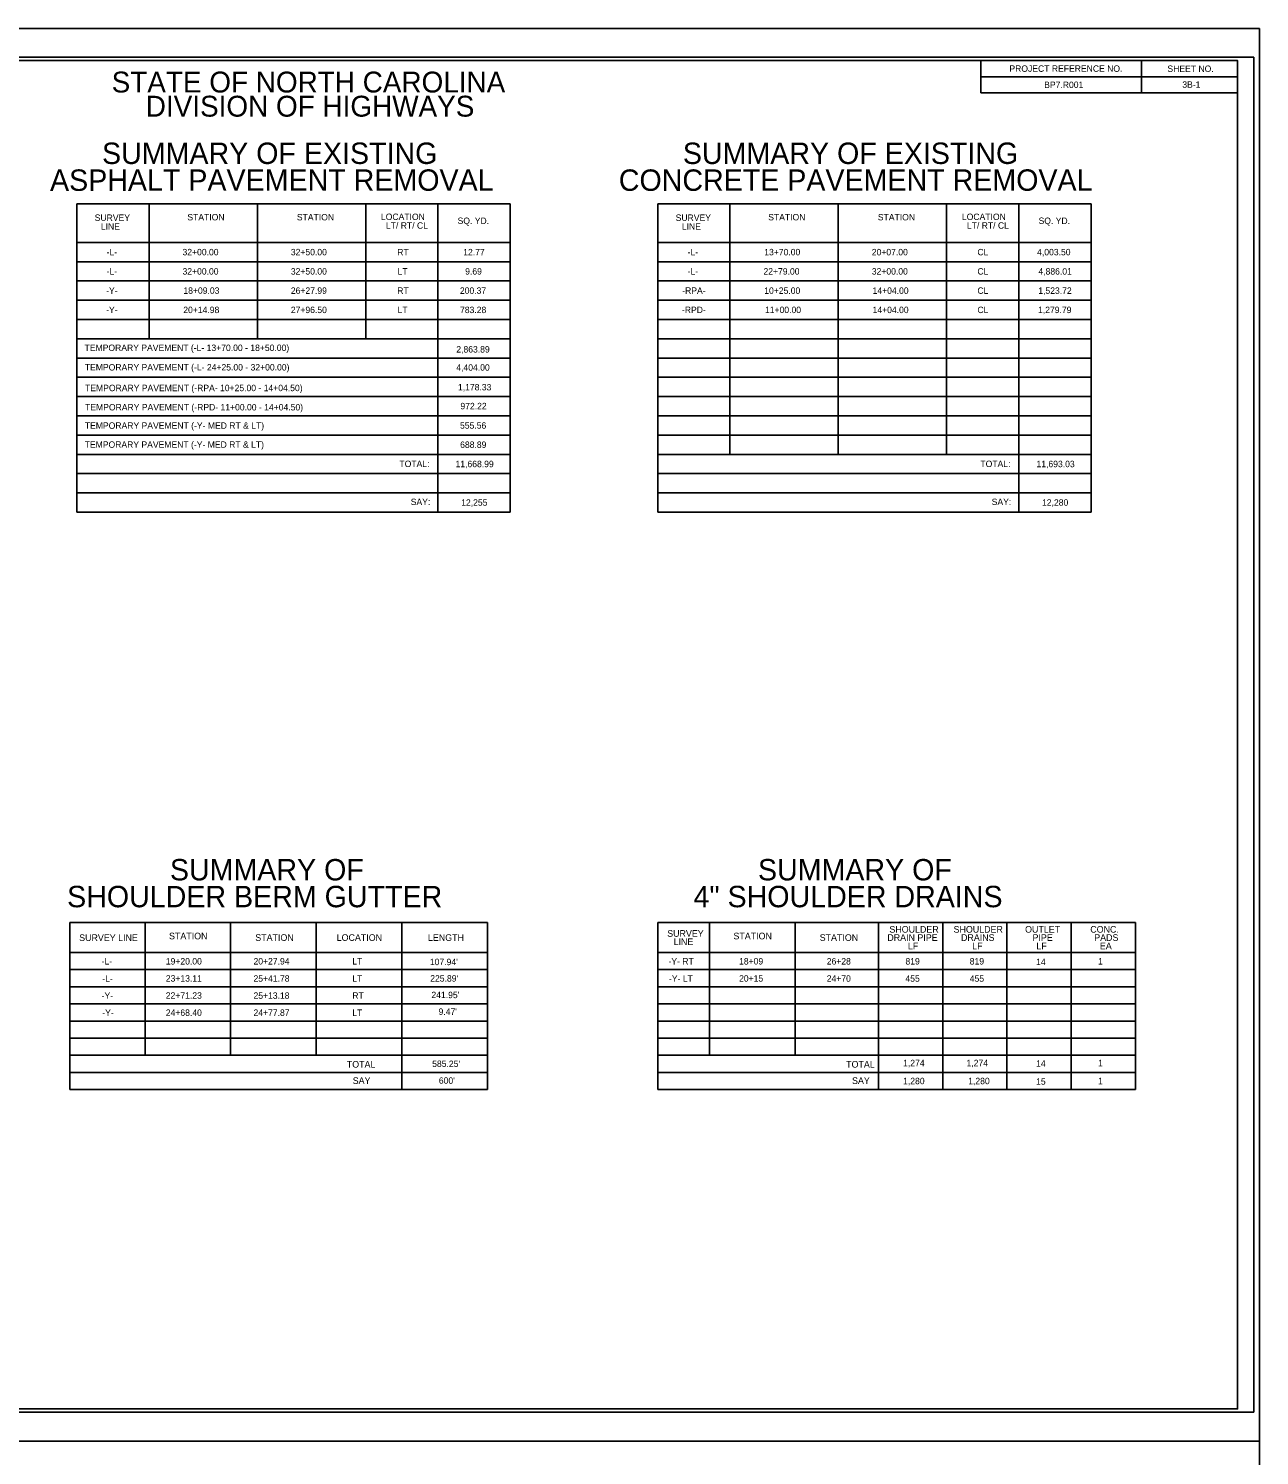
# Model space of a CAD drawing. Extents: x 1730642 to 1732326, y 538795 to 540995.
# Drawn here: x 1731367 to 1732326, y 539884 to 540995 of the extents above; entities that cross this region are included whole.
import ezdxf

# ---------------------------------------------------------------- set-up
doc = ezdxf.new("R2010")
doc.units = 0
for name, color, linetype in [('Default', 7, 'Continuous'), ('Old_Level_40', 7, 'Continuous'), ('Old_Level_44', 7, 'Continuous'), ('Sheet Cutting Line CELL', 7, 'Continuous'), ('Sheet Data Field CELL', 7, 'Continuous'), ('Sheet Pipe Summary CELL', 7, 'Continuous'), ('Sheet Pipe Summary Grid CELL', 7, 'Continuous'), ('Sheet Summary Combination CELL', 7, 'Continuous'), ('Sheet Summary Earthwork CELL', 7, 'Continuous'), ('Sheet Summary Guardrail CELL', 7, 'Continuous')]:
    doc.layers.add(name, color=color, linetype=linetype)

msp = doc.modelspace()

# ---------------------------------------------------------------- linework, layer by layer
at = {"layer": 'Old_Level_40'}
for p, q in [((1732233.5, 540970.4), (1732233.5, 540945.4)), ((1732108.5, 540957.9), (1732308.5, 540957.9)), ((1732108.5, 540945.4), (1732308.5, 540945.4)), ((1731573.6, 540858.8), (1731573.6, 540858.8)), ((1731581.1, 540858.6), (1731581.1, 540858.6)), ((1731592, 540858.9), (1731592, 540858.9)), ((1731598.7, 540858.8), (1731598.7, 540858.8)), ((1732026.2, 540858.8), (1732026.2, 540858.8)), ((1732033.7, 540858.6), (1732033.7, 540858.6)), ((1732044.6, 540858.9), (1732044.6, 540858.9)), ((1732051.3, 540858.8), (1732051.3, 540858.8))]:
    msp.add_line(p, q, dxfattribs=at)
for points in [[(1732308.5, 540970.4), (1730808.5, 540970.4), (1730808.5, 539920.4), (1732308.5, 539920.4)], [(1732108.5, 540970.4), (1732308.5, 540970.4), (1732308.5, 540945.4), (1732108.5, 540945.4)]]:
    msp.add_lwpolyline(points, close=True, dxfattribs=at)
at = {"layer": 'Old_Level_44'}
for p, q in [((1731404.1, 540858.8), (1731741.7, 540858.8)), ((1731404.1, 540858.8), (1731404.1, 540618.8)), ((1731460.4, 540858.8), (1731460.4, 540753.8)), ((1731544.8, 540858.8), (1731544.8, 540753.8)), ((1731629.2, 540858.8), (1731629.2, 540753.8)), ((1731685.5, 540858.8), (1731685.5, 540618.8)), ((1731741.7, 540858.8), (1731741.7, 540618.8)), ((1731856.7, 540858.8), (1732194.3, 540858.8)), ((1731856.7, 540858.8), (1731856.7, 540618.8)), ((1731913, 540858.8), (1731913, 540663.8)), ((1731997.4, 540858.8), (1731997.4, 540663.8)), ((1732081.8, 540858.8), (1732081.8, 540663.8)), ((1732138, 540858.8), (1732138, 540618.8)), ((1732194.3, 540858.8), (1732194.3, 540618.8)), ((1731404.1, 540828.8), (1731741.7, 540828.8)), ((1731856.7, 540828.8), (1732194.3, 540828.8)), ((1731404.1, 540813.8), (1731741.7, 540813.8)), ((1731856.7, 540813.8), (1732194.3, 540813.8)), ((1731404.1, 540798.8), (1731741.7, 540798.8)), ((1731856.7, 540798.8), (1732194.3, 540798.8)), ((1731404.1, 540783.8), (1731741.7, 540783.8)), ((1731856.7, 540783.8), (1732194.3, 540783.8)), ((1731404.1, 540768.8), (1731741.7, 540768.8)), ((1731856.7, 540768.8), (1732194.3, 540768.8)), ((1731404.1, 540753.8), (1731741.7, 540753.8)), ((1731856.7, 540753.8), (1732194.3, 540753.8)), ((1731404.1, 540738.8), (1731741.7, 540738.8)), ((1731856.7, 540738.8), (1732194.3, 540738.8)), ((1731404.1, 540723.8), (1731741.7, 540723.8)), ((1731856.7, 540723.8), (1732194.3, 540723.8)), ((1731404.1, 540708.8), (1731741.7, 540708.8)), ((1731856.7, 540708.8), (1732194.3, 540708.8)), ((1731404.1, 540693.8), (1731741.7, 540693.8)), ((1731856.7, 540693.8), (1732194.3, 540693.8)), ((1731404.1, 540678.8), (1731741.7, 540678.8)), ((1731856.7, 540678.8), (1732194.3, 540678.8)), ((1731404.1, 540663.8), (1731741.7, 540663.8)), ((1731856.7, 540663.8), (1732194.3, 540663.8)), ((1731404.1, 540648.8), (1731741.7, 540648.8)), ((1731856.7, 540648.8), (1732194.3, 540648.8)), ((1731404.1, 540633.8), (1731741.7, 540633.8)), ((1731856.7, 540633.8), (1732194.3, 540633.8)), ((1731404.1, 540618.8), (1731741.7, 540618.8)), ((1731856.7, 540618.8), (1732194.3, 540618.8))]:
    msp.add_line(p, q, dxfattribs=at)
at = {"layer": 'Sheet Cutting Line CELL'}
for points in [[(1730641.5, 540995.4), (1732325.5, 540995.4), (1732325.5, 539895.4), (1730641.5, 539895.4)], [(1730641.5, 539895.4), (1732325.5, 539895.4), (1732325.5, 538795.4), (1730641.5, 538795.4)]]:
    msp.add_lwpolyline(points, close=True, dxfattribs=at)
at = {"layer": 'Sheet Data Field CELL'}
for p, q in [((1731398.6, 540169.1), (1731398.6, 540299.1)), ((1731398.6, 540299.1), (1731724, 540299.1)), ((1731724, 540169.1), (1731724, 540299.1)), ((1731856.7, 540169.1), (1731856.7, 540299.1)), ((1731856.7, 540299.1), (1732182.2, 540299.1)), ((1731724, 540275.8), (1731398.6, 540275.8)), ((1732228.9, 540275.8), (1731856.7, 540275.8)), ((1731398.6, 540262.5), (1731724, 540262.5)), ((1731856.7, 540262.5), (1732228.9, 540262.5)), ((1731724, 540249.1), (1731398.6, 540249.1)), ((1732228.9, 540249.1), (1731856.7, 540249.1)), ((1731724, 540235.8), (1731398.6, 540235.8)), ((1732228.9, 540235.8), (1731856.7, 540235.8)), ((1731724, 540222.5), (1731398.6, 540222.5)), ((1732228.9, 540222.5), (1731856.7, 540222.5)), ((1731398.6, 540209.1), (1731724, 540209.1)), ((1731856.7, 540209.1), (1732228.9, 540209.1)), ((1731398.6, 540195.8), (1731724, 540195.8)), ((1731856.7, 540195.8), (1732228.9, 540195.8)), ((1731724, 540182.5), (1731398.6, 540182.5)), ((1732228.9, 540182.5), (1731856.7, 540182.5)), ((1731398.6, 540169.1), (1731724, 540169.1)), ((1731856.7, 540169.1), (1732228.9, 540169.1))]:
    msp.add_line(p, q, dxfattribs=at)
for points in [[(1731457.4, 540195.8), (1731457.4, 540299.1), (1731524, 540299.1), (1731524, 540195.8)], [(1731590.7, 540195.8), (1731590.7, 540299.1), (1731657.4, 540299.1), (1731657.4, 540169.1)], [(1731897, 540195.8), (1731897, 540299.1), (1731963.7, 540299.1), (1731963.7, 540195.8)], [(1732028.8, 540169.1), (1732028.8, 540299.1), (1732078.8, 540299.1), (1732078.8, 540169.1)], [(1732078.8, 540169.1), (1732078.8, 540299.1), (1732128.8, 540299.1), (1732128.8, 540169.1)], [(1732128.8, 540169.1), (1732128.8, 540299.1), (1732178.9, 540299.1), (1732178.9, 540169.1)], [(1732178.9, 540169.1), (1732178.9, 540299.1), (1732228.9, 540299.1), (1732228.9, 540169.1)]]:
    msp.add_lwpolyline(points, dxfattribs=at)
at = {"layer": 'Sheet Pipe Summary CELL'}
msp.add_lwpolyline([(1732321, 540973), (1730654.5, 540973), (1730654.5, 539917.9), (1732321, 539917.9)], close=True, dxfattribs=at)
at = {"layer": 'Sheet Pipe Summary Grid CELL'}
for points in [[(1732325.5, 540995.4), (1730641.5, 540995.4), (1730641.5, 539895.4), (1732325.5, 539895.4)], [(1732325.5, 539895.4), (1730641.5, 539895.4), (1730641.5, 538795.4), (1732325.5, 538795.4)]]:
    msp.add_lwpolyline(points, close=True, dxfattribs=at)
at = {"layer": 'Sheet Summary Earthwork CELL'}
for p, q in [((1732325.5, 540995.4), (1730641.5, 540995.4)), ((1730641.5, 539895.4), (1732325.5, 539895.4))]:
    msp.add_line(p, q, dxfattribs=at)

# ---------------------------------------------------------------- texts
at = {"layer": 'Default'}
msp.add_text('3B-1', height=5, dxfattribs=at).set_placement((1732265.4, 540949.3))
at = {"layer": 'Old_Level_40'}
for s, height, p in [('PROJECT REFERENCE NO.', 5, (1732130.7, 540961.7)), ('SHEET NO.', 5, (1732253.8, 540961.6)), ('STATE OF NORTH CAROLINA', 16.25, (1731431.3, 540945.6)), ('DIVISION OF HIGHWAYS', 16.25, (1731457.9, 540926.8)), ('SURVEY', 5, (1731418.1, 540845.6)), ('STATION', 5, (1731490.3, 540846)), ('STATION', 5, (1731575.6, 540846)), ('LOCATION', 5, (1731641.1, 540846.3)), ('LT/ RT/ CL', 5, (1731645, 540839.5)), ('SURVEY', 5, (1731870.7, 540845.6)), ('STATION', 5, (1731942.8, 540846)), ('STATION', 5, (1732028.2, 540846)), ('LOCATION', 5, (1732093.7, 540846.3)), ('LT/ RT/ CL', 5, (1732097.6, 540839.5)), ('LINE', 5, (1731422.9, 540838.8)), ('LINE', 5, (1731875.5, 540838.8)), ('-L-', 5, (1731427.4, 540818.8)), ('32+00.00', 5, (1731486.5, 540818.8)), ('32+50.00', 5, (1731570.9, 540818.8)), ('RT', 5, (1731653.8, 540818.8)), ('12.77', 5, (1731705.2, 540818.8)), ('-L-', 5, (1731880, 540818.8)), ('13+70.00', 5, (1731939.7, 540818.8)), ('20+07.00', 5, (1732023.5, 540818.8)), ('CL', 5, (1732105.8, 540818.8)), ('4,003.50', 5, (1732152.3, 540818.8)), ('-L-', 5, (1731427.4, 540803.8)), ('32+00.00', 5, (1731486.5, 540803.8)), ('32+50.00', 5, (1731570.9, 540803.8)), ('LT', 5, (1731654.1, 540803.8)), ('9.69', 5, (1731706.7, 540803.8)), ('-L-', 5, (1731880, 540803.8)), ('22+79.00', 5, (1731939.1, 540803.8)), ('32+00.00', 5, (1732023.5, 540803.8)), ('CL', 5, (1732105.8, 540803.8)), ('4,886.01', 5, (1732153.3, 540803.8)), ('-Y-', 5, (1731427, 540788.8)), ('18+09.03', 5, (1731487.2, 540788.8)), ('26+27.99', 5, (1731570.9, 540788.8)), ('RT', 5, (1731653.8, 540788.8)), ('200.37', 5, (1731702.6, 540788.8)), ('-RPA-', 5, (1731875.8, 540788.8)), ('10+25.00', 5, (1731939.7, 540788.8)), ('14+04.00', 5, (1732024.1, 540788.8)), ('CL', 5, (1732105.8, 540788.8)), ('1,523.72', 5, (1732153.2, 540788.8)), ('-Y-', 5, (1731427, 540773.8)), ('20+14.98', 5, (1731487.1, 540773.8)), ('27+96.50', 5, (1731570.9, 540773.8)), ('LT', 5, (1731654.1, 540773.8)), ('783.28', 5, (1731702.7, 540773.8)), ('-RPD-', 5, (1731875.6, 540773.8)), ('11+00.00', 5, (1731940.3, 540773.8)), ('14+04.00', 5, (1732024.1, 540773.8)), ('CL', 5, (1732105.8, 540773.8)), ('1,279.79', 5, (1732153, 540773.8)), ('TEMPORARY PAVEMENT (-L- 13+70.00 - 18+50.00)', 5, (1731410.2, 540744.3)), ('2,863.89', 5, (1731699.8, 540743.1)), ('TEMPORARY PAVEMENT (-L- 24+25.00 - 32+00.00)', 5, (1731410.4, 540729.1)), ('4,404.00', 5, (1731699.8, 540729)), ('TEMPORARY PAVEMENT (-RPA- 10+25.00 - 14+04.50)', 5, (1731410.6, 540713)), ('1,178.33', 5, (1731701.1, 540713.6)), ('TEMPORARY PAVEMENT (-RPD- 11+00.00 - 14+04.50)', 5, (1731410.6, 540698)), ('972.22', 5, (1731703, 540698.9)), ('TEMPORARY PAVEMENT (-Y- MED RT & LT)', 5, (1731410.4, 540683.7)), ('555.56', 5, (1731702.7, 540683.8)), ('TEMPORARY PAVEMENT (-Y- MED RT & LT)', 5, (1731410.3, 540668.9)), ('688.89', 5, (1731702.8, 540668.8)), ('TOTAL:', 5, (1731655.5, 540653.9)), ('11,668.99', 5, (1731699.2, 540653.8)), ('TOTAL:', 5, (1732108.1, 540653.9)), ('11,693.03', 5, (1732151.8, 540653.8)), ('SAY:', 5, (1731664.3, 540624.3)), ('12,255', 5, (1731703.6, 540623.8)), ('SAY:', 5, (1732116.9, 540624.3)), ('12,280', 5, (1732156.1, 540623.8))]:
    msp.add_text(s, height=height, dxfattribs=at).set_placement(p)
for s, p in [('SUMMARY OF EXISTING', (1731423.8, 540889.9)), ('SUMMARY OF EXISTING', (1731876.3, 540889.9)), ('ASPHALT PAVEMENT REMOVAL', (1731383.3, 540869)), ('CONCRETE PAVEMENT REMOVAL', (1731826.4, 540869))]:
    msp.add_text(s, height=16.667, rotation=0.0119, dxfattribs=at).set_placement(p)
at = {"layer": 'Old_Level_44'}
for p in [(1731700.8, 540843.2), (1732153.4, 540843.2)]:
    msp.add_text('SQ. YD.', height=5, dxfattribs=at).set_placement(p)
at = {"layer": 'Sheet Data Field CELL'}
for s, height, p in [('SUMMARY OF ', 16.667, (1731476.7, 540332)), ('SUMMARY OF ', 16.667, (1731934.8, 540332)), ('SHOULDER BERM GUTTER', 16.667, (1731396.6, 540311.1)), ('4" SHOULDER DRAINS', 16.667, (1731884.6, 540311.1)), ('SURVEY LINE', 5.167, (1731406, 540284.8)), ('STATION', 5.17, (1731476, 540286.1)), ('STATION', 5.17, (1731543.2, 540284.9)), ('LOCATION', 5.17, (1731606.6, 540284.9)), ('LENGTH', 5.17, (1731677.7, 540284.9)), ('SURVEY ', 5.17, (1731864.1, 540288.1)), ('STATION', 5.17, (1731915.7, 540286.1)), ('STATION', 5.17, (1731982.9, 540284.9)), ('DRAIN PIPE', 5.17, (1732035.6, 540284.9)), ('SHOULDER', 5.17, (1732037.2, 540291.3)), ('SHOULDER', 5.17, (1732087.2, 540291.3)), ('DRAINS', 5.17, (1732093, 540284.9)), ('OUTLET ', 5.17, (1732142.9, 540291.3)), ('PIPE', 5.17, (1732148.7, 540284.9)), ('CONC.', 5.17, (1732193.7, 540291.3)), ('PADS', 5.17, (1732196.8, 540284.9)), ('LINE', 5.17, (1731869.1, 540281.6)), ('LF', 5.17, (1732051.6, 540278.4)), ('LF', 5.17, (1732101.7, 540278.4)), ('LF', 5.17, (1732151.7, 540278.4)), ('EA', 5.17, (1732201.2, 540278.4)), ('TOTAL', 5.17, (1731614.5, 540186.2)), ('TOTAL', 5.17, (1732003.5, 540186.2)), ('SAY', 5.17, (1731619.1, 540173.5)), ('SAY', 5.17, (1732008.1, 540173.5))]:
    msp.add_text(s, height=height, dxfattribs=at).set_placement(p)
at = {"layer": 'Sheet Summary Combination CELL'}
msp.add_text('BP7.R001', height=5, dxfattribs=at).set_placement((1732157.8, 540949.1))
at = {"layer": 'Sheet Summary Guardrail CELL'}
for s, p in [('-L-', (1731423.5, 540266.5)), ('19+20.00', (1731473.5, 540266.5)), ('20+27.94', (1731541.8, 540266.5)), ('LT', (1731618.8, 540266.5)), ("107.94'", (1731679.2, 540266)), ('-Y- RT', (1731865.1, 540266.5)), ('18+09', (1731920.1, 540266.5)), ('26+28', (1731988.4, 540266.5)), ('819', (1732049.7, 540266.5)), ('819', (1732099.8, 540266.5)), ('14', (1732151.5, 540266)), ('1', (1732199.8, 540266.5)), ('-L-', (1731424, 540253.1)), ('23+13.11', (1731473.5, 540253.2)), ('25+41.78', (1731541.8, 540253.1)), ('LT', (1731618.8, 540253.1)), ("225.89'", (1731679.5, 540253.2)), ('-Y- LT', (1731865.5, 540253.1)), ('20+15', (1731920.1, 540253.2)), ('24+70', (1731988.4, 540253.1)), ('455', (1732049.7, 540253.1)), ('455', (1732099.8, 540253.1)), ('-Y-', (1731423.5, 540239.8)), ('22+71.23', (1731473.5, 540239.9)), ('25+13.18', (1731541.8, 540239.8)), ('RT', (1731618.8, 540239.8)), ("241.95'", (1731680.4, 540240.3)), ('-Y-', (1731424, 540226.5)), ('24+68.40', (1731473.5, 540226.5)), ('24+77.87', (1731541.8, 540226.5)), ('LT', (1731618.8, 540226.5)), ("9.47'", (1731686, 540227.3)), ("585.25'", (1731681, 540186.7)), ('1,274', (1732047.9, 540187.3)), ('1,274', (1732097.3, 540187.3)), ('14', (1732151.5, 540186.9)), ('1', (1732199.8, 540187.3)), ("600'", (1731686.2, 540173.6)), ('1,280', (1732047.9, 540173.3)), ('1,280', (1732098.6, 540173.3)), ('15', (1732151.5, 540172.9)), ('1', (1732199.8, 540173.3))]:
    msp.add_text(s, height=5, dxfattribs=at).set_placement(p)

doc.saveas('drawing.dxf')
